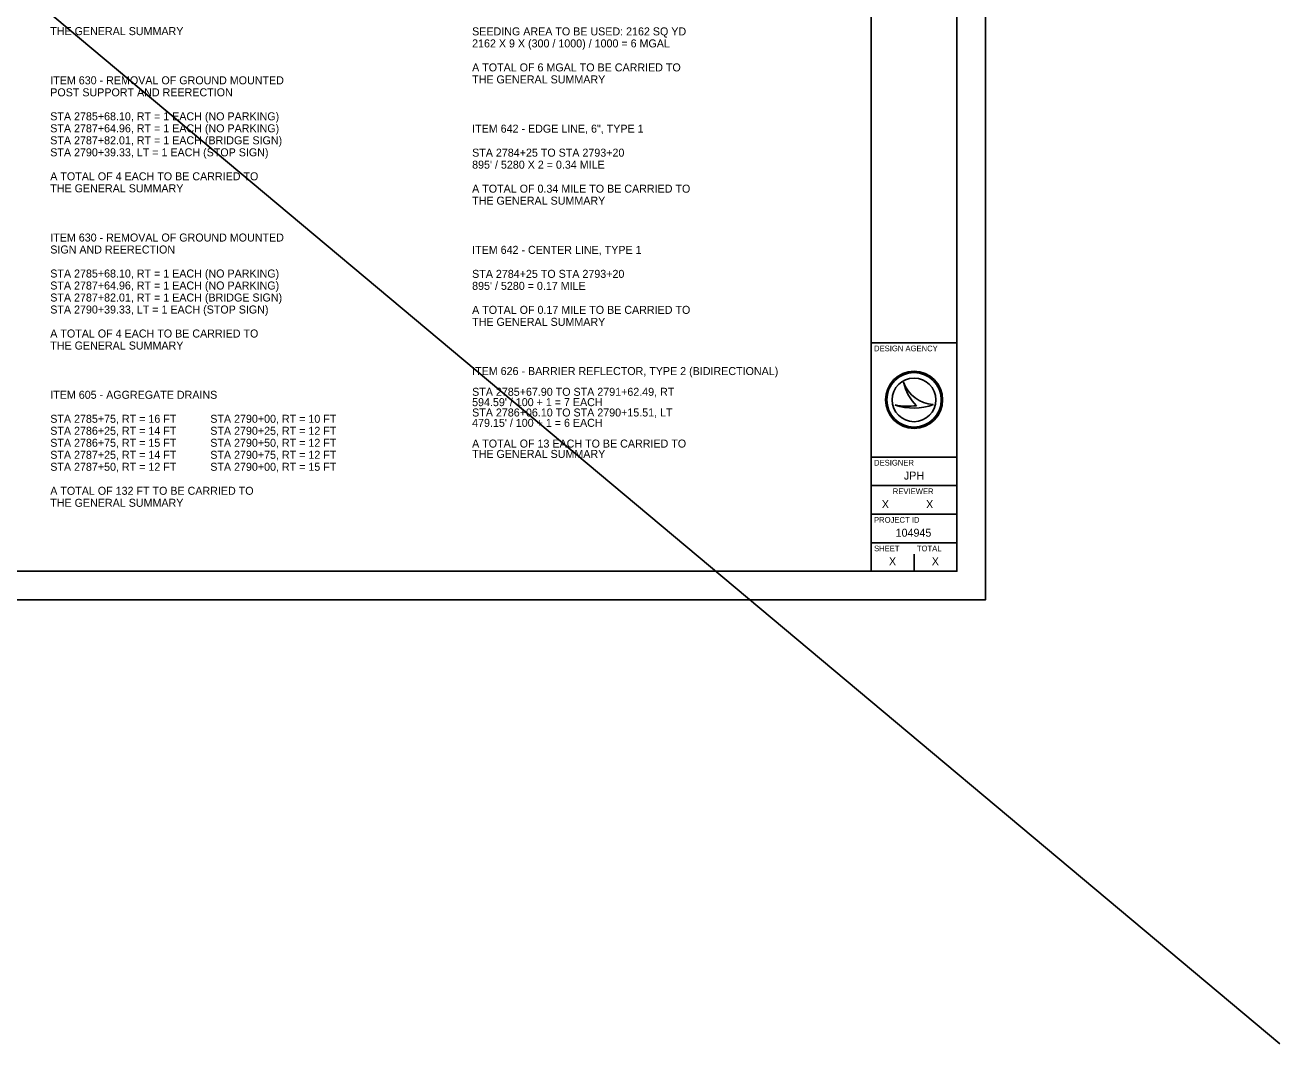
# Model space of a CAD drawing. Extents: x 0 to 126, y 0 to 48.
# Drawn here: x 101.92 to 123.87, y 12.21 to 30.04 of the extents above; entities that cross this region are included whole.
import ezdxf

# ---------------------------------------------------------------- set-up
doc = ezdxf.new("R2010")
doc.units = 0
for name, color, linetype in [('SH_Border', 7, 'Continuous'), ('SH_Cut_Line', 7, 'Continuous'), ('SH_Data', 7, 'Continuous'), ('SH_Text', 7, 'Continuous'), ('TX_P_1', 7, 'Continuous')]:
    doc.layers.add(name, color=color, linetype=linetype)

msp = doc.modelspace()

# ---------------------------------------------------------------- linework, layer by layer
at = {"layer": 'SH_Border'}
for p, q in [((116.721, 20.477), (116.721, 41.477)), ((116.721, 24.477), (118.221, 24.477)), ((116.721, 22.477), (118.221, 22.477)), ((116.721, 21.977), (118.221, 21.977)), ((116.721, 21.477), (118.221, 21.477)), ((116.721, 20.977), (118.221, 20.977))]:
    msp.add_line(p, q, dxfattribs=at)
msp.add_lwpolyline([(86.221, 41.477), (118.221, 41.477), (118.221, 20.477), (86.221, 20.477)], close=True, dxfattribs=at)
at = {"layer": 'SH_Cut_Line'}
msp.add_lwpolyline([(84.721, 19.977), (118.721, 19.977), (118.721, 41.977), (84.721, 41.977)], close=True, dxfattribs=at)
at = {"layer": 'SH_Data'}
for p, q in [((117.289, 23.787), (117.289, 23.787)), ((117.138, 23.387), (117.138, 23.387)), ((117.471, 23.477), (117.471, 23.477)), ((117.808, 23.396), (117.808, 23.396)), ((117.096, 20.652), (117.096, 20.652)), ((117.471, 20.477), (117.471, 20.777))]:
    msp.add_line(p, q, dxfattribs=at)
for radius in [0.5, 0.477, 0.477, 0.382]:
    msp.add_circle((117.471, 23.477), radius, dxfattribs=at)
for centre, radius, start, end in [((117.837, 23.975), 0.58, 198.9257, 198.9319), ((118.068, 23.947), 0.796, 191.6379, 191.6421), ((117.837, 23.975), 0.58, 198.9319, 267.1657), ((118.068, 23.947), 0.796, 191.6421, 226.0947), ((117.461, 24.347), 1.013, 251.4576, 290.0832), ((117.369, 24.632), 1.266, 259.4964, 259.4995), ((117.461, 24.347), 1.013, 251.4527, 251.4576), ((117.369, 24.632), 1.266, 259.4995, 276.6672)]:
    msp.add_arc(centre, radius, start, end, dxfattribs=at)
at = {"layer": 'SH_Text'}
msp.add_line((81.554, 47.674), (123.873, 12.206), dxfattribs=at)

# ---------------------------------------------------------------- texts
at = {"layer": 'SH_Data'}
for s, height, p in [('DESIGN AGENCY', 0.1, (116.771, 24.327)), ('DESIGNER', 0.1, (116.771, 22.327)), ('JPH', 0.14, (117.294, 22.082)), ('REVIEWER', 0.1, (117.099, 21.827)), ('X', 0.14, (116.907, 21.582)), ('X', 0.14, (117.682, 21.582)), ('PROJECT ID', 0.1, (116.771, 21.327)), ('104945', 0.14, (117.149, 21.082)), ('SHEET', 0.1, (116.771, 20.827)), ('TOTAL', 0.1, (117.521, 20.827)), ('X', 0.14, (117.032, 20.582)), ('X', 0.14, (117.782, 20.582))]:
    msp.add_text(s, height=height, dxfattribs=at).set_placement(p)
at = {"layer": 'TX_P_1'}
for s, p in [('THE GENERAL SUMMARY', (102.356, 29.86)), ('SEEDING AREA TO BE USED: 2162 SQ YD', (109.738, 29.855)), ('2162 X 9 X (300 / 1000) / 1000 = 6 MGAL', (109.738, 29.645)), ('A TOTAL OF 6 MGAL TO BE CARRIED TO', (109.738, 29.225)), ('ITEM 630 - REMOVAL OF GROUND MOUNTED', (102.356, 28.999)), ('THE GENERAL SUMMARY', (109.738, 29.015)), ('POST SUPPORT AND REERECTION', (102.356, 28.789)), ('STA 2785+68.10, RT = 1 EACH (NO PARKING)', (102.356, 28.369)), ('STA 2787+64.96, RT = 1 EACH (NO PARKING)', (102.356, 28.159)), ('ITEM 642 - EDGE LINE, 6", TYPE 1', (109.738, 28.153)), ('STA 2787+82.01, RT = 1 EACH (BRIDGE SIGN)', (102.356, 27.949)), ('STA 2790+39.33, LT = 1 EACH (STOP SIGN)', (102.356, 27.739)), ('STA 2784+25 TO STA 2793+20', (109.738, 27.733)), ("895' / 5280 X 2 = 0.34 MILE", (109.738, 27.523)), ('A TOTAL OF 4 EACH TO BE CARRIED TO', (102.356, 27.319)), ('THE GENERAL SUMMARY', (102.356, 27.109)), ('A TOTAL OF 0.34 MILE TO BE CARRIED TO', (109.738, 27.103)), ('THE GENERAL SUMMARY', (109.738, 26.893)), ('ITEM 630 - REMOVAL OF GROUND MOUNTED', (102.356, 26.248)), ('SIGN AND REERECTION', (102.356, 26.038)), ('ITEM 642 - CENTER LINE, TYPE 1', (109.738, 26.032)), ('STA 2785+68.10, RT = 1 EACH (NO PARKING)', (102.356, 25.618)), ('STA 2784+25 TO STA 2793+20', (109.738, 25.612)), ('STA 2787+64.96, RT = 1 EACH (NO PARKING)', (102.356, 25.408)), ("895' / 5280 = 0.17 MILE", (109.738, 25.402)), ('STA 2787+82.01, RT = 1 EACH (BRIDGE SIGN)', (102.356, 25.198)), ('STA 2790+39.33, LT = 1 EACH (STOP SIGN)', (102.356, 24.988)), ('A TOTAL OF 0.17 MILE TO BE CARRIED TO', (109.738, 24.982)), ('THE GENERAL SUMMARY', (109.738, 24.772)), ('A TOTAL OF 4 EACH TO BE CARRIED TO', (102.356, 24.568)), ('THE GENERAL SUMMARY', (102.356, 24.358)), ('ITEM 626 - BARRIER REFLECTOR, TYPE 2 (BIDIRECTIONAL)', (109.738, 23.911)), ('ITEM 605 - AGGREGATE DRAINS', (102.356, 23.496)), ("594.59' / 100 + 1 = 7 EACH", (109.738, 23.367)), ('STA 2785+67.90 TO STA 2791+62.49, RT', (109.738, 23.548)), ('STA 2786+06.10 TO STA 2790+15.51, LT', (109.738, 23.186)), ('STA 2785+75, RT = 16 FT', (102.356, 23.076)), ('STA 2790+00, RT = 10 FT', (105.156, 23.076)), ("479.15' / 100 + 1 = 6 EACH", (109.738, 23.005)), ('STA 2786+25, RT = 14 FT', (102.356, 22.866)), ('STA 2790+25, RT = 12 FT', (105.156, 22.866)), ('STA 2786+75, RT = 15 FT', (102.356, 22.656)), ('STA 2790+50, RT = 12 FT', (105.156, 22.656)), ('A TOTAL OF 13 EACH TO BE CARRIED TO', (109.738, 22.642)), ('STA 2787+25, RT = 14 FT', (102.356, 22.446)), ('STA 2790+75, RT = 12 FT', (105.156, 22.446)), ('THE GENERAL SUMMARY', (109.738, 22.461)), ('STA 2787+50, RT = 12 FT', (102.356, 22.236)), ('STA 2790+00, RT = 15 FT', (105.156, 22.236)), ('A TOTAL OF 132 FT TO BE CARRIED TO', (102.356, 21.816)), ('THE GENERAL SUMMARY', (102.356, 21.606))]:
    msp.add_text(s, height=0.14, dxfattribs=at).set_placement(p)

doc.saveas('drawing.dxf')
